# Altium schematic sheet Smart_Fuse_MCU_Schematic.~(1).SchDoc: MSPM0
size 431 x 279 mm; Date: Not shown in title block; ApprovedBy: Not shown in title block; CheckedBy: Not shown in title block; Author: Not shown in title block; CompanyName: Not shown in title block; DrawnBy: Robert Smith; Engineer: Not shown in title block; Organization: Not shown in title block; Address1: Not shown in title block; Address2: Not shown in title block; Address3: Not shown in title block; Address4: Not shown in title block; DocumentNumber: 1; Revision: Use project parameter SCH_Rev; SheetNumber: 3; SheetTotal: 4; PageSetup: Record=PageOptions¦CenterHorizontal=True¦CenterVertical=True¦PrintScale=1.00¦XCorrection=1.00¦YCorrection=1.00¦PrintKind=0¦BorderSize=5000000¦LeftOffset=0¦BottomOffset=0¦Orientation=2¦PaperLength=1000¦PaperWidth=1000¦Scale=100¦PaperSource=15¦PrintQuality=600¦MediaType=1¦DitherType=10¦PaperKind=Letter¦PrintScaleMode=1
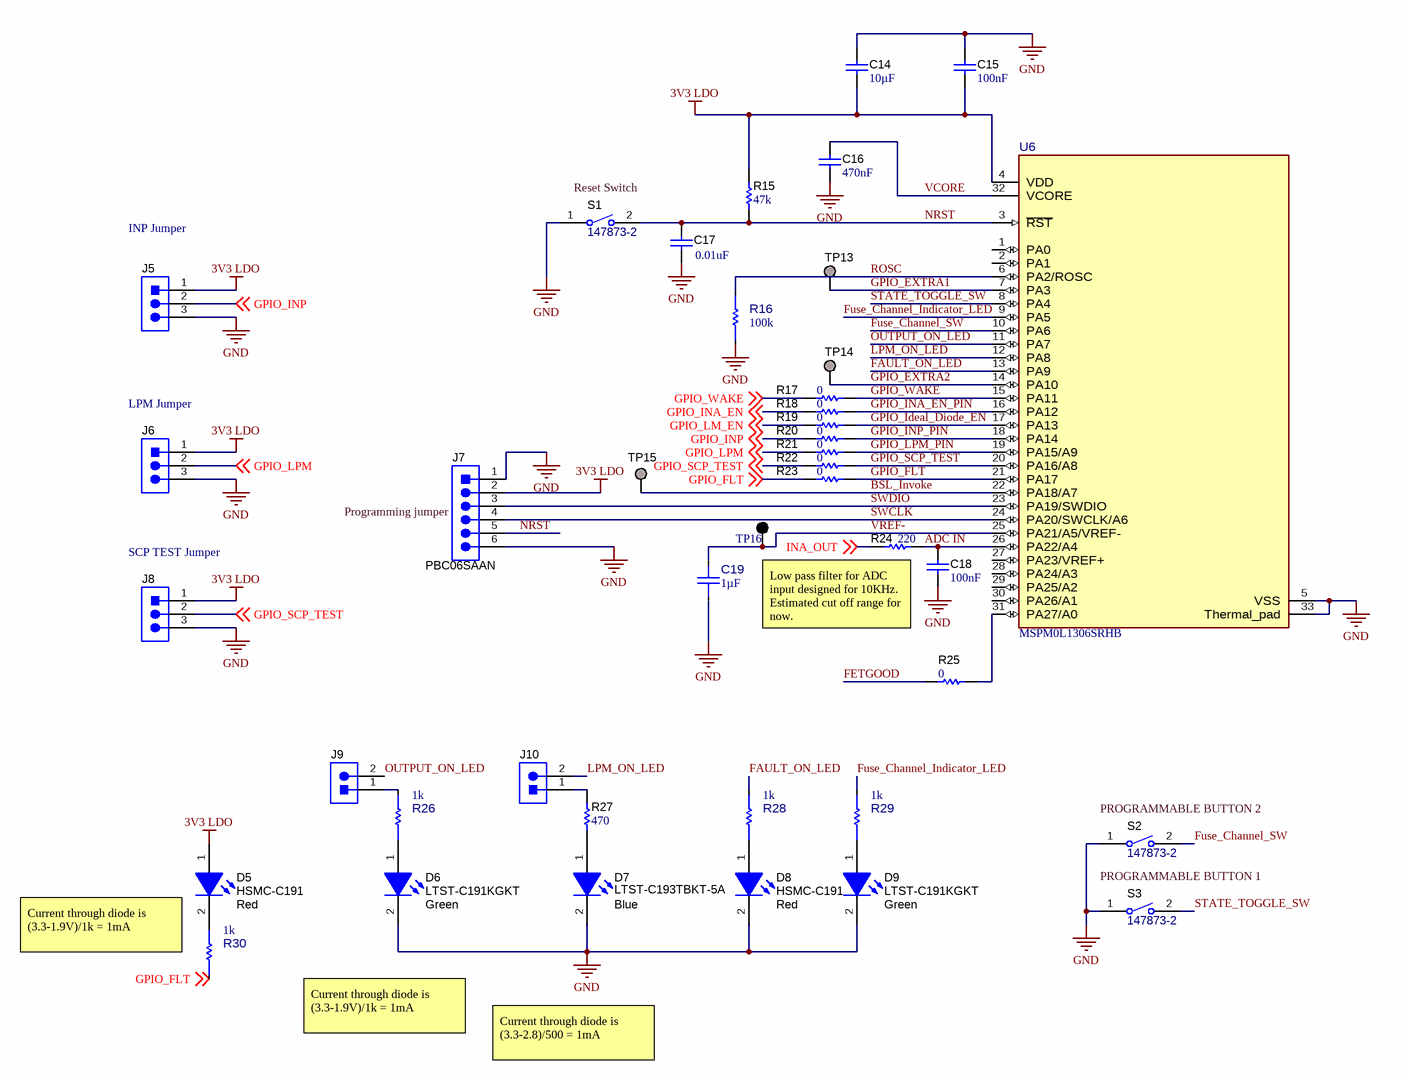
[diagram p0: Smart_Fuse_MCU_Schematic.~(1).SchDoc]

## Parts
C14  Cap_F: 10µF  [0805_HV]  (hidden comment: JMJ212CB7106KGHT)
C15  Cap_F: 100nF  [0603]  (hidden comment: 06035C104KAZ2A)
C16  Cap_F: 470nF  [0603]  (hidden comment: CGA3E3X7R1H474M080AE)
C17  ValueDisplayed: 0.01uF  [0603]  (hidden comment: C0603C103J3GECAUTO)
C18  Cap_F: 100nF  [0603]  (hidden comment: 06035C104KAZ2A)
C19  Cap_F: 1µF  [FP-UMK212B7105KGHT_0805-MFG]  (hidden comment: UMK212B7105KGHT)
D5  HSMC-C191  value Red  [HSMx-C191_Red]
D6  LTST-C191KGKT  value Green  [LTST-C191_Green]
D7  LTST-C193TBKT-5A  value Blue  [LTST-C193_Blue]
D8  HSMC-C191  value Red  [HSMx-C191_Red]
D9  LTST-C191KGKT  value Green  [LTST-C191_Green]
J5  TSW-103-07-T-S  [Samtec_TSW-103-07-T-S]  (value not drawn)
J6  TSW-103-07-T-S  [Samtec_TSW-103-07-T-S]  (value not drawn)
J7  PBC06SAAN  [Sullins_PxC06SAAN]
J8  TSW-103-07-T-S  [Samtec_TSW-103-07-T-S]  (value not drawn)
J9  SL 11 112 02G  [Fischer_SL-11-112-02G]  (value not drawn)
J10  SL 11 112 02G  [Fischer_SL-11-112-02G]  (value not drawn)
R15  ValueDisplayed: 47k  [0603]  (hidden comment: CRCW060347K0JNEA)
R16  value 100k  [FP-ERJ-PB3B1003V_0603-MFG]  (hidden comment: ERJ-PB3B1003V)
R17  ValueDisplayed: 0  [0603]  (hidden comment: ERJ-3GEY0R00V)
R18  ValueDisplayed: 0  [0603]  (hidden comment: ERJ-3GEY0R00V)
R19  ValueDisplayed: 0  [0603]  (hidden comment: ERJ-3GEY0R00V)
R20  ValueDisplayed: 0  [0603]  (hidden comment: ERJ-3GEY0R00V)
R21  ValueDisplayed: 0  [0603]  (hidden comment: ERJ-3GEY0R00V)
R22  ValueDisplayed: 0  [0603]  (hidden comment: ERJ-3GEY0R00V)
R23  ValueDisplayed: 0  [0603]  (hidden comment: ERJ-3GEY0R00V)
R24  ValueDisplayed: 220  [0603]  (hidden comment: RG1608P-221-B-T5)
R25  ValueDisplayed: 0  [0603]  (hidden comment: ERJ-3GEY0R00V)
R26  value 1k  [FP-RNCF0603TKW1K00_0603-MFG]  (hidden comment: RNCF0603TKW1K00)
R27  ValueDisplayed: 470  [0603]  (hidden comment: CRCW0603470RJNEA)
R28  value 1k  [FP-RNCF0603TKW1K00_0603-MFG]  (hidden comment: RNCF0603TKW1K00)
R29  value 1k  [FP-RNCF0603TKW1K00_0603-MFG]  (hidden comment: RNCF0603TKW1K00)
R30  value 1k  [FP-RNCF0603TKW1K00_0603-MFG]  (hidden comment: RNCF0603TKW1K00)
S1  147873-2  [SW_147873-2]
S2  147873-2  [SW_147873-2]
S3  147873-2  [SW_147873-2]
TP13  TP_SM_1MM  [TP_SM_1MM]  (value not drawn)  (no BOM)
TP14  TP_SM_1MM  [TP_SM_1MM]  (value not drawn)  (no BOM)
TP15  TP_SM_1MM  [TP_SM_1MM]  (value not drawn)  (no BOM)
TP16  5011  [Keystone5011]  (value not drawn)
U6  MSPM0L1306SRHB  [RHB0032N-MFG]

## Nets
3V3 LDO: C14.2 C15.2 D5.1(A) J5.1 J6.1 J7.2 J8.1 R15.2 U6.4(VDD)
GND: C14.1 C15.1 C16.2 C17.2 C18.2 C19.1 D6.2(K) D7.2(K) D8.2(K) D9.2(K) J5.3 J6.3 J7.1 J7.6 J8.3 R16.1 S1.1 S2.1 S3.1 U6.5(VSS) U6.33(Thermal_pad)
ADC IN: C18.1 R24.2 U6.26(PA22/A4)
BSL_Invoke: TP15.1 U6.22(PA18/A7)
FAULT_ON_LED: R28.2 U6.13(PA9)
FETGOOD: R25.1
Fuse_Channel_Indicator_LED: R29.2 U6.9(PA5)
Fuse_Channel_SW: S2.2 U6.10(PA6)
GPIO_EXTRA1: TP13.1 U6.7(PA3)
GPIO_EXTRA2: TP14.1 U6.14(PA10)
GPIO_FLT: R23.1 R23.2 R30.1 U6.21(PA17) ; off-sheet GPIO_FLT
GPIO_Ideal_Diode_EN: R19.2 U6.17(PA13)
GPIO_INA_EN: R18.1 ; off-sheet GPIO_INA_EN
GPIO_INA_EN_PIN: R18.2 U6.16(PA12)
GPIO_INP: J5.2 R20.1 ; off-sheet GPIO_INP
GPIO_INP_PIN: R20.2 U6.18(PA14)
GPIO_LM_EN: R19.1 ; off-sheet GPIO_LM_EN
GPIO_LPM: J6.2 R21.1 ; off-sheet GPIO_LPM
GPIO_LPM_PIN: R21.2 U6.19(PA15/A9)
GPIO_SCP_TEST: J8.2 R22.1 R22.2 U6.20(PA16/A8) ; off-sheet GPIO_SCP_TEST
GPIO_WAKE: R17.1 R17.2 U6.15(PA11) ; off-sheet GPIO_WAKE
INA_OUT: R24.1 ; off-sheet INA_OUT
LPM_ON_LED: J10.2 U6.12(PA8)
NRST: C17.1 J7.5 R15.1 S1.2 U6.3(~{RST})
OUTPUT_ON_LED: J9.2 U6.11(PA7)
ROSC: R16.2 U6.6(PA2/ROSC)
STATE_TOGGLE_SW: S3.2 U6.8(PA4)
SWCLK: J7.4 U6.24(PA20/SWCLK/A6)
SWDIO: J7.3 U6.23(PA19/SWDIO)
VCORE: C16.1 U6.32(VCORE)
VREF-: C19.2 TP16.1 U6.25(PA21/A5/VREF-)
NetD5_2: D5.2(K) R30.2
NetD6_1: D6.1(A) R26.1
NetD7_1: D7.1(A) R27.1
NetD8_1: D8.1(A) R28.1
NetD9_1: D9.1(A) R29.1
NetJ9_1: J9.1 R26.2
NetJ10_1: J10.1 R27.2
NetR25_2: R25.2 U6.31(PA27/A0)

Not connected (* = marked no-connect by the designer): U6 1(PA0) 2(PA1) 27(PA23/VREF+) 28(PA24/A3) 29(PA25/A2) 30(PA26/A1)

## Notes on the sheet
- INP Jumper
- (near S1) Reset Switch
- (near J6) LPM Jumper
- (near J8) SCP TEST Jumper
- (near J7) Programming jumper
- (near R24) Low pass filter for ADC input designed for 10KHz. Estimated cut off range for now.
- (near S2) PROGRAMMABLE BUTTON 2
- PROGRAMMABLE BUTTON 1
- Current through diode is (3.3-1.9V)/1k = 1mA
- Current through diode is (3.3-2.8)/500 = 1mA

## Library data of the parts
C14 = CMP-0081188-1: CAP, CERM, 10 µF, 6.3 V,+/- 10%, X7R, AEC-Q200 Grade 1, 0805; Manufacturer: Taiyo Yuden; TaMin_C: -55°C; Polarized: N; SizeAreaWB_mm2: 6.75; U/M: EA; Value: 10uF; TaMax_C: 125°C; SizeZ_mm: 1.45; SizeX_mm: 2; SizeY_mm: 1.25; Cap_Case: 0805; Value2: 6.3V; SizeArea_mm2: 2.5; AEC Qualified: Y; AEC Grade: 1; AEC Category: Q200
C15 C18 = CMP-0079095-1: CAP, CERM, 0.1 µF, 50 V,+/- 10%, X7R, AEC-Q200 Grade 1, 0603; Manufacturer: AVX; SizeAreaWB_mm2: 4.68; SizeArea_mm2: 1.28; AEC Qualified: Y; AEC Category: Q200; Value: 0.1uF; TaMax_C: 125°C; SizeZ_mm: 1; Polarized: N; TaMin_C: -55°C; VDC_V: 50V; SizeY_mm: 0.8; U/M: EA; SizeX_mm: 1.6; ValueDisplayed: 0.1µF
C16 = CMP-0007098-4: CAP, CERM, 0.47 uF, 50 V, +/- 20%, X7R, AEC-Q200 Grade 1, 0603; Manufacturer: TDK; TaMin_C: -55°C; Polarized: N; SizeAreaWB_mm2: 4.68; Value1: Unknown; U/M: EA; Value: 0.47uF; TaMax_C: 125°C; SizeZ_mm: 1; SizeX_mm: 1.6; SizeY_mm: 0.8; Value2: 50V; SizeArea_mm2: 1.28; AEC Qualified: Y; AEC Category: Q200
C17 = CMP-0006849-4: CAP, CERM, 0.01 uF, 25 V, +/- 5%, C0G/NP0, AEC-Q200 Grade 1, 0603; Manufacturer: Kemet; TaMin_C: -55°C; Polarized: N; SizeAreaWB_mm2: 4.68; Value1: Unknown; U/M: EA; Value: 0.01uF; TaMax_C: 125°C; SizeZ_mm: 1; SizeX_mm: 1.6; SizeY_mm: 0.8; Value2: 25V; SizeArea_mm2: 1.28; AEC Qualified: Y; Cap_F: 10nF; AEC Category: Q200
C19 = CMP-0098253-1: Multilayer Ceramic Capacitor 1 uF 50V X7R 10% SMD 0805 Automotive T/R; Manufacturer: Taiyo Yuden; Tolerance_%: 0.1%; AEC Qualified: Yes; SizeZ_mm: 1.35mm; ValueDisplayed: 1uF; Value: 1µF; TempCo: 0.15; AEC Grade: Grade 1
D5 D8 = CMP-0078541-2: LED, Red, SMD; Manufacturer: Avago; Vf_V: 1.9V; SizeX_mm: 1.6; SizeY_mm: 0.8; Tjmax_C: 95°C; Io_A: 20mA; SizeAreaWB_mm2: 4.68; Value1: W; Angle: 170; SizeArea_mm2: 1.28; Vr_V: 5V; Type: AlInGaP; SizeZ_mm: 0.7
D6 D9 = CMP-0078478-2: LED, Green, SMD; Manufacturer: Lite-On; Value2: 2V; Vr_V: 5V; Ir_A: 10µA; Value1: 0.075W; Tjmax_C: 85°C; Green_Lifecycle: Not Set; Angle: 130; Type: AlInGaP; Power_TotalModule: 75mW; Io_A: 30mA; Green_REACh: Incomplete
D7 = CMP-0002938-3: LED, Blue, SMD; Manufacturer: Lite-On; Angle: 130; Power_TotalModule: 76mW; Type: InGaN; Tjmax_C: 80°C; Value1: 0.076W; Io_A: 5mA; Ir_A: 10µA; LuminousIntensity_IV: 15; Value2: 2.8V
J5 J6 J8 = CMP-0075530-2: Header, 2.54 mm, 3x1, Tin, TH; Manufacturer: Samtec; Pitch_mm: 2.54; Cert_VDE: N; Gender: Male; Cert_CSA: Y; Voltage_V: 550V; Green_REACh: Passed; Current_A: 6.3A; Green_Lifecycle: Active; Row_Count: 1
J7 = CMP-0054603-1: Header, 2.54mm, 6x1, Gold, TH; Manufacturer: Sullins Connector Solutions; CNHeader: TRUE; Current_A: 3A; Green_Lifecycle: Not Set; Shrouded: N; Gender: Male; Green_REACh: Incomplete; Row_Count: 1; Pitch_mm: 2.54; CT: FALSE; Cert_UL: Y
J9 J10 = CMP-0075049-1: Header, 2.54mm, 2x1, Gold, TH; Manufacturer: Fischer Elektronik; CT: False; CNHeader: True
R15 = CMP-0025814-4: RES, 47 k, 5%, 0.1 W, AEC-Q200 Grade 0, 0603; Manufacturer: Vishay-Dale; Power_W: 100mW; TempCo: 200 ppm/C; Value_Code: 47k0; Value: 47k; EIA_Code: E24; SizeX_mm: 1.6; SizeY_mm: 0.8; SizeZ_mm: 1; Value2: 0.1W; SizeArea_mm2: 1.28; AEC Qualified: Y; VDC_V: 75V; AEC Category: Q200; AEC Grade: 0
R16 = CMP-0092407-1: Res Thick Film 0603 100K Ohm 0.1% 0.2W(1/5W) ±50ppm/°C Pad SMD Automotive T/R; Manufacturer: Panasonic; Power_W: 200mW; VDC_V: 150V; AEC Qualified: Yes; SizeZ_mm: 0.55mm; AEC Grade: Grade 0
R17-R23 R25 = CMP-0025874-4: RES, 0, 5%, 0.1 W, AEC-Q200 Grade 0, 0603; Manufacturer: Panasonic; Power_W: 100mW; TempCo: 600 ppm/C; Value_Code: 0000; Value: 0; EIA_Code: E24; SizeX_mm: 1.6; SizeY_mm: 0.8; SizeZ_mm: 1; Value2: 0.1W; SizeArea_mm2: 1.28; AEC Qualified: Y; VDC_V: 50V; AEC Category: Q200; SizeAreaWB_mm2: 4.68
R24 = CMP-0023472-3: RES, 220, 0.1%, 0.1 W, 0603; Manufacturer: Susumu Co Ltd; Power_W: 100mW; TempCo: 25 ppm/C; Value_Code: 220R; U/M: EA; Value: 220; SizeX_mm: 1.6; SizeY_mm: 0.8; SizeZ_mm: 1; Value2: 0.1W; SizeArea_mm2: 1.28; VDC_V: 75V; AEC Category: Q200
R26 R28-R30 = CMP-0091933-1: 1 kOhms ±0.01% 0.1W, 1/10W Chip Resistor 0603 (1608 Metric) Automotive AEC-Q200 Thin Film; Manufacturer: Stackpole Electronics; VDC_V: 75V; AEC Qualified: Yes; Power_W: 100mW; AEC Grade: Grade 0; TempCo: 2ppm/°C; SizeZ_mm: 0.55mm
R27 = CMP-0025813-4: RES, 470, 5%, 0.1 W, AEC-Q200 Grade 0, 0603; Manufacturer: Vishay-Dale; Power_W: 100mW; TempCo: 200 ppm/C; Value_Code: 470R; Value: 470; EIA_Code: E24; SizeX_mm: 1.6; SizeY_mm: 0.8; SizeZ_mm: 1; Value2: 0.1W; SizeArea_mm2: 1.28; AEC Qualified: Y; VDC_V: 75V; AEC Category: Q200; AEC Grade: 0
S1-S3 = CMP-0002294-1: Switch, SPST, Off-On, 50 mA,24V, SMD; Manufacturer: TE Connectivity; CurrentRating_mA: 50A; PositionCount: 1; SizeX_mm: 6.8; SizeY_mm: 3.5; SizeZ_mm: 4.65; SizeArea_mm2: 23.8; SizeAreaWB_mm2: 48.4
TP13-TP15 = CMP-0003825-1: 1mm Test Point, SMT; Manufacturer: Any
TP16 = CMP-0055148-2: Test Point, Multipurpose, Black, TH; Manufacturer: Keystone Electronics; CNHeader: FALSE; ContactFinish: Silver; Green_REACh: Passed; Green_Lifecycle: Active; CT: TRUE
U6 = CMP-0093968-1: MSPM0L130x Mixed-Signal Microcontrollers; Manufacturer: Texas Instruments; Number Of Pwm Channels: 8; TJmax_C: +130°C; Interface: I2C,SPI,UART,LIN,IrDA,SMBus; Number Of I2C Channels: 2; Memory Size: 64KBytes; Core Architecture: ARM Cortex-M0+; Number Of Spi Channels: 1; Min Supply Voltage: 1.62V; Ram Size: 4KBytes; Data Bus Width: 32bits; TaMax_C: +125°C; Frequency_Fixed: 32MHz; Memory Type: FLASH; Number Of Adc Channels: 10; Standoff Height: 0mm; AEC Qualified: No; Number Of I/Os: 28; TaMin_C: -40°C; SizeZ_mm: 1mm; Max Supply Voltage: 3.6V; Number Of Timers/Counters: 4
